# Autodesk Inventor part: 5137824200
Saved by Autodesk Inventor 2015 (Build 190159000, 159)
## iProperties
Created: 2020-07
Part Number: 5137824200
Checked By: TraceParts S.A.
Material: Generic
Catalog Web Link: www.traceparts.com
Document SubType Name: Modeling
Designer: TraceParts
Density: 1 g/cm^3
Appearance: Default
Company: TraceParts S.A.
Author: TraceParts
REFERENCE: 5137824200
DESIGN: CVAT/4-9000/500 N D PTC 1,1KW (230/400V) 50HZ - 5137824200
SUPPLIER: Soler & Palau
TraceParts.PartNumber: 10-14122018-105188
TraceParts.PartTitle: CVAT-N
TraceParts.InstanceId: 10-14122018-105188B7OH5JHF42LAMHIZ1VMK0WRVJ
TraceParts.PartStatus: Published
TraceParts.PartVersion: 1.0.4
TRACEPARTS: TRACEPARTS
TraceParts.PartLanguage: en
TraceParts.ClassPath: SOLER_PALAU:10-14122018-105188
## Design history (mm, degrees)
feature "5137824200"
body "Solid1"
